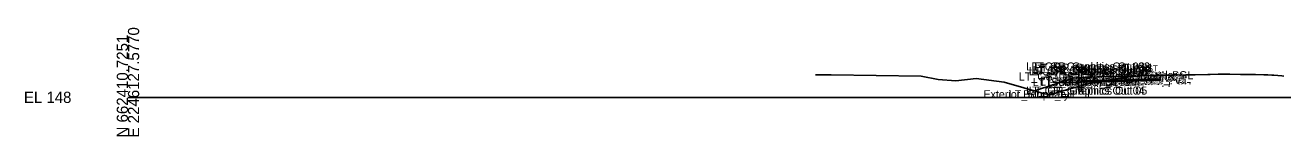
# Model space of a CAD drawing. Extents: x -26 to 603, y -10 to 9526.
# Drawn here: x -25.7 to 288.6, y 4490.3 to 4517.3 of the extents above; entities that cross this region are included whole.
import ezdxf

# ---------------------------------------------------------------- set-up
doc = ezdxf.new("R2010")
doc.units = 0
for name, color, linetype in [('Default', 7, 'Continuous'), ('Exist Cross Section Cell', 7, 'Continuous'), ('Exist XS Ground Line', 7, 'Continuous'), ('Prop CMT Guardrail Graphics', 7, 'Continuous'), ('Prop CMT Pvmt Course 1', 7, 'Continuous'), ('Prop CMT Pvmt Course 2', 7, 'Continuous'), ('Prop CMT Pvmt Course 3', 7, 'Continuous'), ('Prop CMT Pvmt Surface', 7, 'Continuous'), ('Prop CMT Pvmt Surface Shoulder', 7, 'Continuous'), ('Prop CMT Shld Paved Course 1', 7, 'Continuous'), ('Prop CMT Shld Paved Course 2', 7, 'Continuous'), ('Prop CMT Shld Paved Course 3', 7, 'Continuous'), ('Prop CMT Slope Grass', 7, 'Continuous'), ('Prop CMT Subgrade Earthwork', 7, 'Continuous'), ('Prop XS SE Text', 7, 'Continuous'), ('Prop XS Side Slope Text', 7, 'Continuous'), ('Scratch_Level_2', 7, 'Continuous')]:
    doc.layers.add(name, color=color, linetype=linetype)

msp = doc.modelspace()

# ---------------------------------------------------------------- linework, layer by layer
at = {"layer": 'Exist Cross Section Cell'}
msp.add_line((0, 4500), (300, 4500), dxfattribs=at)
at = {"layer": 'Exist XS Ground Line'}
for p, q in [((171.87, 4505.6), (175.76, 4505.59)), ((175.76, 4505.59), (198.24, 4505.24)), ((198.24, 4505.24), (202.5, 4504.41)), ((202.5, 4504.41), (206.93, 4504.14)), ((206.93, 4504.14), (211.99, 4504.69)), ((211.99, 4504.69), (219.01, 4503.82)), ((243.3, 4503.94), (250.11, 4505.21)), ((250.11, 4505.21), (250.66, 4505.11)), ((250.66, 4505.11), (251.22, 4505.16)), ((251.22, 4505.16), (251.88, 4505.25)), ((251.88, 4505.25), (253.41, 4505.36)), ((253.41, 4505.36), (255.39, 4505.45)), ((255.39, 4505.45), (256.82, 4505.47)), ((256.82, 4505.47), (257.33, 4505.47)), ((257.33, 4505.47), (258, 4505.52)), ((258, 4505.52), (259.03, 4505.51)), ((259.03, 4505.51), (260.61, 4505.55)), ((260.61, 4505.55), (261.12, 4505.49)), ((261.12, 4505.49), (261.42, 4505.58)), ((261.42, 4505.58), (262.19, 4505.59)), ((262.19, 4505.59), (263.54, 4505.56)), ((263.54, 4505.56), (264.4, 4505.57)), ((264.4, 4505.57), (266.72, 4505.62)), ((266.72, 4505.62), (269.89, 4505.69)), ((269.89, 4505.69), (270.49, 4505.7)), ((270.49, 4505.7), (272.49, 4505.75)), ((272.49, 4505.75), (272.9, 4505.76)), ((272.9, 4505.76), (273.43, 4505.78)), ((273.43, 4505.78), (274.72, 4505.78)), ((274.72, 4505.78), (275.38, 4505.77)), ((275.38, 4505.77), (278.05, 4505.73)), ((278.05, 4505.73), (280.87, 4505.69)), ((280.87, 4505.69), (281.82, 4505.67)), ((281.82, 4505.67), (283.88, 4505.63)), ((283.88, 4505.63), (284.32, 4505.61)), ((284.32, 4505.61), (284.88, 4505.6)), ((284.88, 4505.6), (285.91, 4505.54)), ((285.91, 4505.54), (286.36, 4505.5)), ((286.36, 4505.5), (288.4, 4505.33)), ((288.4, 4505.33), (288.87, 4505.3)), ((219.01, 4503.82), (228.78, 4500.96)), ((230.36, 4500.6), (232.94, 4501.35)), ((232.94, 4501.35), (233.43, 4501.5)), ((233.43, 4501.5), (238.18, 4502.9)), ((238.18, 4502.9), (238.81, 4503.09)), ((238.81, 4503.09), (243.3, 4503.94)), ((228.78, 4500.96), (230.36, 4500.6))]:
    msp.add_line(p, q, dxfattribs=at)
at = {"layer": 'Prop CMT Guardrail Graphics'}
for points in [[(237.61, 4501.55), (237.61, 4507.55)], [(237.61, 4507.55), (238.94, 4507.55), (239.21, 4507.26)], [(239.21, 4506.68), (238.94, 4506.39), (238.28, 4506.39)], [(238.28, 4506.39), (238.28, 4501.55)], [(239.21, 4507.26), (238.94, 4506.97)], [(238.94, 4506.97), (239.21, 4506.68)], [(238.28, 4501.55), (237.61, 4501.55)]]:
    msp.add_lwpolyline(points, dxfattribs=at)
at = {"layer": 'Prop CMT Pvmt Course 1'}
for points in [[(258, 4505.52), (249.5, 4505.31)], [(249.5, 4505.31), (249.5, 4504.39)], [(249.5, 4504.39), (258, 4504.61)], [(258, 4504.61), (258, 4505.52)]]:
    msp.add_lwpolyline(points, dxfattribs=at)
at = {"layer": 'Prop CMT Pvmt Course 2'}
for points in [[(258, 4504.61), (249.5, 4504.39)], [(249.5, 4504.39), (249.5, 4504.06)], [(258, 4504.27), (258, 4504.61)], [(249.5, 4504.06), (258, 4504.27)]]:
    msp.add_lwpolyline(points, dxfattribs=at)
at = {"layer": 'Prop CMT Pvmt Course 3'}
for points in [[(258, 4504.27), (249.5, 4504.06)], [(249.5, 4504.06), (258, 4504.27)], [(249.5, 4504.06), (249.5, 4504.06)], [(258, 4504.27), (258, 4504.27)]]:
    msp.add_lwpolyline(points, dxfattribs=at)
at = {"layer": 'Prop CMT Pvmt Surface'}
msp.add_lwpolyline([(258, 4505.52), (249.5, 4505.31)], dxfattribs=at)
at = {"layer": 'Prop CMT Pvmt Surface Shoulder'}
msp.add_lwpolyline([(249.5, 4505.31), (239.21, 4505.05)], dxfattribs=at)
at = {"layer": 'Prop CMT Shld Paved Course 1'}
for p, q in [((239.21, 4505.05), (238.27, 4504.11)), ((249.5, 4505.31), (245.5, 4505.21))]:
    msp.add_line(p, q, dxfattribs=at)
for points in [[(244.56, 4504.27), (249.5, 4504.39)], [(249.5, 4504.39), (249.5, 4505.31)]]:
    msp.add_lwpolyline(points, dxfattribs=at)
at = {"layer": 'Prop CMT Shld Paved Course 2'}
for p, q in [((249.5, 4504.39), (238.27, 4504.11)), ((238.27, 4504.11), (237.93, 4503.77))]:
    msp.add_line(p, q, dxfattribs=at)
for points in [[(249.5, 4504.06), (249.5, 4504.39)], [(244.22, 4503.93), (249.5, 4504.06)]]:
    msp.add_lwpolyline(points, dxfattribs=at)
at = {"layer": 'Prop CMT Shld Paved Course 3'}
for points in [[(249.5, 4504.06), (244.22, 4503.93), (243.72, 4503.92)], [(243.72, 4503.92), (249.5, 4504.06)], [(243.72, 4503.92), (243.72, 4503.92)], [(249.5, 4504.06), (249.5, 4504.06)]]:
    msp.add_lwpolyline(points, dxfattribs=at)
at = {"layer": 'Prop CMT Slope Grass'}
for points in [[(236.21, 4504.81), (226.59, 4501.61)], [(239.21, 4505.05), (236.21, 4504.81)]]:
    msp.add_lwpolyline(points, dxfattribs=at)
at = {"layer": 'Prop CMT Subgrade Earthwork'}
for points in [[(243.72, 4503.92), (232.7, 4503.64)], [(249.5, 4504.06), (243.72, 4503.92)], [(258, 4504.27), (249.5, 4504.06)]]:
    msp.add_lwpolyline(points, dxfattribs=at)

# ---------------------------------------------------------------- texts
at = {"layer": 'Default'}
msp.add_text('-', height=0.0001, dxfattribs=at).set_placement((0, 4500))
msp.add_text('-', height=0.0001, dxfattribs=at).set_placement((0, 4500))
msp.add_text('-', height=0.0001, dxfattribs=at).set_placement((0, 4500))
msp.add_text('-', height=0.0001, dxfattribs=at).set_placement((0, 4500))
at = {"layer": 'Exist Cross Section Cell'}
for s, p in [('E 2246127.5770', (2.8, 4490)), ('N 662410.7251', (0, 4490))]:
    msp.add_text(s, height=2.8, rotation=90, dxfattribs=at).set_placement(p)
msp.add_text('EL 148', height=2.8, dxfattribs=at).set_placement((-26, 4498.6))
at = {"layer": 'Prop XS SE Text'}
msp.add_text('EXIST', height=1.5, rotation=1.4321, dxfattribs=at).set_placement((251.61, 4506.36))
at = {"layer": 'Prop XS Side Slope Text'}
msp.add_text('3:1', height=1.5, rotation=18.4332, dxfattribs=at).set_placement((230.4, 4503.49))
at = {"layer": 'Scratch_Level_2'}
for s, p in [('LT_GR_Graphics Out 03', (224.51, 4506.69)), ('LT_GR_Graphics Out 06', (225.13, 4505.52)), ('LT_GR_Graphics Out 02', (225.84, 4506.69)), ('LT_GR_Graphics Out 09', (225.84, 4506.1)), ('LT_GR_Graphics Out 07', (225.84, 4505.52)), ('LT_GR_Graphics Out 08', (226.11, 4505.81)), ('LT_GR_Graphics Out 01', (226.68, 4506.4)), ('LT_GS_OS_GR_Face_Graphics', (222.67, 4504.19)), ('LT_Sub_OSS_DLT', (226.15, 4502.79)), ('LT_Sub_Trench_Out', (227.92, 4502.92)), ('LT_PS3_Shelf_Out', (229.7, 4502.92)), ('LT_GS_OS_CTL', (231.58, 4503.95)), ('LT_PS3_OEOP', (234.46, 4502.93)), ('LT_PS2_OEOP', (234.8, 4503.27)), ('LT_PS1_OEOP', (236.3, 4504.21)), ('LT_Sub_OEOT', (239.58, 4503.06)), ('LT_PV2_OEOT', (239.67, 4503.39)), ('LT_PV3_OEOT', (239.67, 4503.06)), ('LT_PV1_OEOT', (240.24, 4504.31)), ('Exterior Boundary', (242.15, 4504.52)), ('LT_Sub_PGL', (249.12, 4503.27)), ('LT_PV2_PGL', (249.22, 4503.61)), ('LT_PV3_PGL', (249.22, 4503.27)), ('LT_PV1_PGL', (249.78, 4504.52)), ('Exterior Boundary', (213.8, 4499.76)), ('LT_Slope_Fill', (220.17, 4499.76)), ('LT_GR_Graphics Out 04', (224.51, 4500.69)), ('LT_GR_Graphics Out 05', (225.17, 4500.69))]:
    msp.add_text(s, height=2, dxfattribs=at).set_placement(p)

doc.saveas('drawing.dxf')
